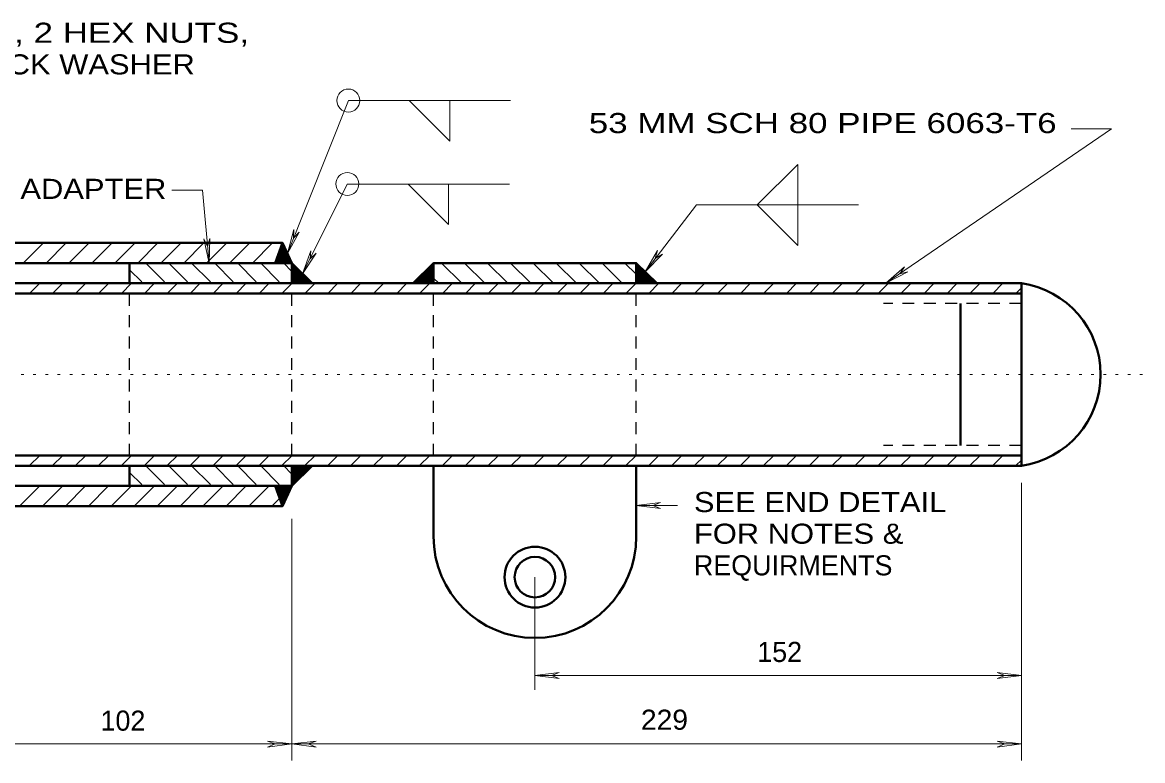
# Model space of a CAD drawing. Extents: x 312583 to 312854, y 144419 to 144597.
# Drawn here: x 312723.42 to 312765.79, y 144492.05 to 144519.98 of the extents above; entities that cross this region are included whole.
import ezdxf

# ---------------------------------------------------------------- set-up
doc = ezdxf.new("R2010")
doc.units = 0
doc.header["$LTSCALE"] = 0.3
doc.linetypes.add('DOTTED', pattern=[1.5, 0.3, -1.2])
doc.linetypes.add('SHORT_DASHED', pattern=[2.7, 1.5, -1.2])
doc.layers.add('1', color=7, linetype='Continuous', lineweight=13)

msp = doc.modelspace()

# ---------------------------------------------------------------- linework, layer by layer
at = {"layer": '1'}
for p, q in [((312735.7482, 144517.0229), (312733.4405, 144511.2346)), ((312741.8815, 144517.0229), (312735.7482, 144517.0229)), ((312756.0802, 144510.1076), (312764.6055, 144515.9572)), ((312763.0799, 144515.9572), (312764.6055, 144515.9572)), ((312735.7022, 144513.8642), (312734.0155, 144510.4679)), ((312741.8355, 144513.8642), (312735.7022, 144513.8642)), ((312748.9119, 144513.0746), (312746.9722, 144510.5446)), ((312755.0452, 144513.0746), (312748.9119, 144513.0746)), ((312733.4405, 144511.2346), (312733.6782, 144512.1392)), ((312733.4405, 144511.2346), (312733.8852, 144512.0472)), ((312733.6782, 144512.1392), (312733.6705, 144511.8172)), ((312733.8852, 144512.0472), (312733.6705, 144511.8172)), ((312723.4432, 144510.8742), (312724.2099, 144511.6409)), ((312724.3095, 144510.8742), (312725.0762, 144511.6409)), ((312725.1759, 144510.8742), (312725.9425, 144511.6409)), ((312726.0422, 144510.8742), (312726.8089, 144511.6409)), ((312726.9162, 144510.8742), (312727.6752, 144511.6409)), ((312727.7825, 144510.8742), (312728.5415, 144511.6409)), ((312728.6489, 144510.8742), (312729.4155, 144511.6409)), ((312729.5152, 144510.8742), (312730.2819, 144511.6409)), ((312730.2742, 144511.7866), (312730.4199, 144511.5029)), ((312730.4735, 144510.8742), (312730.2742, 144511.7866)), ((312730.3815, 144510.8742), (312731.1482, 144511.6409)), ((312730.5042, 144511.8019), (312730.4199, 144511.5029)), ((312730.4735, 144510.8742), (312730.5042, 144511.8019)), ((312731.2479, 144510.8742), (312732.0145, 144511.6409)), ((312732.1142, 144510.8742), (312732.8809, 144511.6409)), ((312732.9882, 144510.8742), (312733.3945, 144511.2882)), ((312734.0155, 144510.4679), (312734.3299, 144511.3419)), ((312734.0155, 144510.4679), (312734.5292, 144511.2422)), ((312734.3299, 144511.3419), (312734.2992, 144511.0352)), ((312734.5292, 144511.2422), (312734.2992, 144511.0352)), ((312746.9722, 144510.5446), (312747.4399, 144511.3496)), ((312746.9722, 144510.5446), (312747.6239, 144511.2116)), ((312747.4399, 144511.3496), (312747.3555, 144511.0506)), ((312747.6239, 144511.2116), (312747.3555, 144511.0506)), ((312728.7945, 144510.1689), (312728.0815, 144510.8742)), ((312729.6609, 144510.1689), (312728.9479, 144510.8742)), ((312730.5272, 144510.1689), (312729.8142, 144510.8742)), ((312731.3935, 144510.1689), (312730.6882, 144510.8742)), ((312732.2599, 144510.1689), (312731.5469, 144510.8819)), ((312733.1262, 144510.1689), (312732.4209, 144510.8819)), ((312733.6092, 144510.5522), (312733.2872, 144510.8819)), ((312740.0339, 144510.1076), (312739.2672, 144510.8742)), ((312740.9002, 144510.1076), (312740.1335, 144510.8742)), ((312741.7742, 144510.1076), (312741.0075, 144510.8742)), ((312742.6405, 144510.1076), (312741.8739, 144510.8742)), ((312743.5069, 144510.1076), (312742.7402, 144510.8742)), ((312744.3732, 144510.1076), (312743.6065, 144510.8742)), ((312745.2395, 144510.1076), (312744.4729, 144510.8742)), ((312746.1059, 144510.1076), (312745.3392, 144510.8742)), ((312746.6349, 144510.4526), (312746.2055, 144510.8742)), ((312756.0802, 144510.1076), (312756.7779, 144510.7286)), ((312756.7779, 144510.7286), (312756.6015, 144510.4679)), ((312727.9282, 144510.1689), (312727.4682, 144510.6212)), ((312739.1675, 144510.1076), (312738.9682, 144510.3069)), ((312756.0802, 144510.1076), (312756.9082, 144510.5369)), ((312756.9082, 144510.5369), (312756.6015, 144510.4679)), ((312723.6885, 144509.7242), (312724.0719, 144510.1076)), ((312724.5549, 144509.7242), (312724.9382, 144510.1076)), ((312725.4289, 144509.7242), (312725.8122, 144510.1076)), ((312726.2952, 144509.7242), (312726.6785, 144510.1076)), ((312727.1615, 144509.7242), (312727.5449, 144510.1076)), ((312728.0279, 144509.7242), (312728.4112, 144510.1076)), ((312728.8942, 144509.7242), (312729.2775, 144510.1076)), ((312729.7605, 144509.7242), (312730.1439, 144510.1076)), ((312730.6269, 144509.7242), (312731.0102, 144510.1076)), ((312731.5009, 144509.7242), (312731.8842, 144510.1076)), ((312732.3672, 144509.7242), (312732.7505, 144510.1076)), ((312733.2335, 144509.7242), (312733.6169, 144510.1076)), ((312734.0999, 144509.7242), (312734.4832, 144510.1076)), ((312734.9662, 144509.7242), (312735.3495, 144510.1076)), ((312735.8325, 144509.7242), (312736.2159, 144510.1076)), ((312736.6989, 144509.7242), (312737.0822, 144510.1076)), ((312737.5729, 144509.7242), (312737.9562, 144510.1076)), ((312738.4392, 144509.7242), (312738.8225, 144510.1076)), ((312739.3055, 144509.7242), (312739.6889, 144510.1076)), ((312740.1719, 144509.7242), (312740.5552, 144510.1076)), ((312741.0382, 144509.7242), (312741.4215, 144510.1076)), ((312741.9045, 144509.7242), (312742.2879, 144510.1076)), ((312742.7709, 144509.7242), (312743.1542, 144510.1076)), ((312743.6449, 144509.7242), (312744.0282, 144510.1076)), ((312744.5035, 144509.7242), (312744.8945, 144510.1076)), ((312745.3775, 144509.7242), (312745.7609, 144510.1076)), ((312746.2439, 144509.7242), (312746.6272, 144510.1076)), ((312747.1102, 144509.7242), (312747.4935, 144510.1076)), ((312747.9765, 144509.7242), (312748.3599, 144510.1076)), ((312748.8429, 144509.7242), (312749.2262, 144510.1076)), ((312749.7092, 144509.7242), (312750.0925, 144510.1076)), ((312750.5755, 144509.7242), (312750.9589, 144510.1076)), ((312751.4495, 144509.7242), (312751.8329, 144510.1076)), ((312752.3159, 144509.7242), (312752.6992, 144510.1076)), ((312753.1822, 144509.7242), (312753.5655, 144510.1076)), ((312754.0485, 144509.7242), (312754.4319, 144510.1076)), ((312754.9149, 144509.7242), (312755.2982, 144510.1076)), ((312755.7812, 144509.7242), (312756.1722, 144510.1076)), ((312756.6475, 144509.7242), (312757.0309, 144510.1076)), ((312757.5215, 144509.7242), (312757.9049, 144510.1076)), ((312758.3879, 144509.7242), (312758.7712, 144510.1076)), ((312759.2542, 144509.7242), (312759.6375, 144510.1076)), ((312760.1205, 144509.7242), (312760.5039, 144510.1076)), ((312760.9869, 144509.7242), (312761.2015, 144509.9389)), ((312723.6885, 144503.2152), (312724.0719, 144503.5986)), ((312724.5549, 144503.2152), (312724.9382, 144503.5986)), ((312725.4289, 144503.2152), (312725.8122, 144503.5986)), ((312726.2952, 144503.2152), (312726.6785, 144503.5986)), ((312727.1615, 144503.2152), (312727.5449, 144503.5986)), ((312728.0279, 144503.2152), (312728.4112, 144503.5986)), ((312728.8942, 144503.2152), (312729.2775, 144503.5986)), ((312729.7605, 144503.2152), (312730.1439, 144503.5986)), ((312730.6269, 144503.2152), (312731.0102, 144503.5986)), ((312731.5009, 144503.2152), (312731.8842, 144503.5986)), ((312732.3672, 144503.2152), (312732.7505, 144503.5986)), ((312733.2335, 144503.2152), (312733.6169, 144503.5986)), ((312734.0999, 144503.2152), (312734.4832, 144503.5986)), ((312734.9662, 144503.2152), (312735.3495, 144503.5986)), ((312735.8325, 144503.2152), (312736.2159, 144503.5986)), ((312736.6989, 144503.2152), (312737.0822, 144503.5986)), ((312737.5729, 144503.2152), (312737.9562, 144503.5986)), ((312738.4392, 144503.2152), (312738.8225, 144503.5986)), ((312739.3055, 144503.2152), (312739.6889, 144503.5986)), ((312740.1719, 144503.2152), (312740.5552, 144503.5986)), ((312741.0382, 144503.2152), (312741.4215, 144503.5986)), ((312741.9045, 144503.2152), (312742.2879, 144503.5986)), ((312742.7709, 144503.2152), (312743.1542, 144503.5986)), ((312743.6449, 144503.2152), (312744.0282, 144503.5986)), ((312744.5035, 144503.2152), (312744.8945, 144503.5986)), ((312745.3775, 144503.2152), (312745.7609, 144503.5986)), ((312746.2439, 144503.2152), (312746.6272, 144503.5986)), ((312747.1102, 144503.2152), (312747.4935, 144503.5986)), ((312747.9765, 144503.2152), (312748.3599, 144503.5986)), ((312748.8429, 144503.2152), (312749.2262, 144503.5909)), ((312749.7092, 144503.2152), (312750.0925, 144503.5909)), ((312750.5755, 144503.2152), (312750.9589, 144503.5986)), ((312751.4495, 144503.2152), (312751.8329, 144503.5986)), ((312752.3159, 144503.2152), (312752.6992, 144503.5986)), ((312753.1822, 144503.2152), (312753.5655, 144503.5986)), ((312754.0485, 144503.2152), (312754.4319, 144503.5986)), ((312754.9149, 144503.2152), (312755.2982, 144503.5986)), ((312755.7812, 144503.2152), (312756.1722, 144503.5986)), ((312756.6475, 144503.2152), (312757.0309, 144503.5986)), ((312757.5215, 144503.2152), (312757.9049, 144503.5986)), ((312758.3879, 144503.2152), (312758.7712, 144503.5986)), ((312759.2542, 144503.2152), (312759.6375, 144503.5986)), ((312760.1205, 144503.2152), (312760.5039, 144503.5986)), ((312728.7945, 144502.5022), (312728.0815, 144503.2076)), ((312729.6609, 144502.5022), (312728.9479, 144503.2076)), ((312730.5272, 144502.5022), (312729.8142, 144503.2076)), ((312731.3935, 144502.5022), (312730.6882, 144503.2076)), ((312732.2599, 144502.5022), (312731.5469, 144503.2152)), ((312733.1262, 144502.5022), (312732.4209, 144503.2152)), ((312733.6092, 144502.8856), (312733.2872, 144503.2152)), ((312760.9869, 144503.2152), (312761.2015, 144503.4222)), ((312727.9282, 144502.5022), (312727.4682, 144502.9546)), ((312723.3052, 144501.6742), (312724.0719, 144502.4409)), ((312724.1715, 144501.6742), (312724.9382, 144502.4409)), ((312725.0455, 144501.6742), (312725.8045, 144502.4409)), ((312725.9119, 144501.6742), (312726.6709, 144502.4409)), ((312726.7782, 144501.6742), (312727.5449, 144502.4409)), ((312727.6445, 144501.6742), (312728.4112, 144502.4409)), ((312728.5109, 144501.6742), (312729.2775, 144502.4409)), ((312729.3772, 144501.6742), (312730.1439, 144502.4409)), ((312730.2435, 144501.6742), (312731.0102, 144502.4409)), ((312731.1175, 144501.6742), (312731.8765, 144502.4409)), ((312731.9762, 144501.6742), (312732.7429, 144502.4409)), ((312732.8502, 144501.6742), (312733.6169, 144502.4409)), ((312761.2015, 144502.5559), (312761.2015, 144492.0526)), ((312746.6349, 144501.7049), (312747.5549, 144501.8199)), ((312747.5549, 144501.8199), (312747.2635, 144501.7049)), ((312748.1989, 144501.7049), (312746.6349, 144501.7049)), ((312746.6349, 144501.7049), (312747.5549, 144501.5899)), ((312747.5549, 144501.5899), (312747.2635, 144501.7049)), ((312733.6015, 144501.1989), (312733.6015, 144492.0526)), ((312742.8015, 144498.9909), (312742.8015, 144494.7282)), ((312742.8015, 144495.2726), (312743.7215, 144495.3876)), ((312742.8015, 144495.2726), (312761.2015, 144495.2726)), ((312742.8015, 144495.2726), (312743.7215, 144495.1576)), ((312743.7215, 144495.3876), (312743.4302, 144495.2726)), ((312743.7215, 144495.1576), (312743.4302, 144495.2726)), ((312760.2815, 144495.3876), (312760.5729, 144495.2726)), ((312761.2015, 144495.2726), (312760.2815, 144495.3876)), ((312760.2815, 144495.1576), (312760.5729, 144495.2726)), ((312761.2015, 144495.2726), (312760.2815, 144495.1576)), ((312732.6815, 144492.7886), (312732.9729, 144492.6812)), ((312733.6015, 144492.6812), (312732.6815, 144492.7886)), ((312732.6815, 144492.5662), (312732.9729, 144492.6812)), ((312733.6015, 144492.6812), (312732.6815, 144492.5662)), ((312733.6015, 144492.6812), (312734.5215, 144492.7886)), ((312733.6015, 144492.6812), (312734.5215, 144492.5662)), ((312734.5215, 144492.7886), (312734.2302, 144492.6812)), ((312734.5215, 144492.5662), (312734.2302, 144492.6812)), ((312760.2815, 144492.7886), (312760.5729, 144492.6812)), ((312761.2015, 144492.6812), (312760.2815, 144492.7886)), ((312760.2815, 144492.5662), (312760.5729, 144492.6812)), ((312761.2015, 144492.6812), (312760.2815, 144492.5662))]:
    msp.add_line(p, q, dxfattribs=at)
at = {"layer": '1', "lineweight": 40}
for p, q in [((312733.2565, 144511.6409), (312718.9199, 144511.6409)), ((312733.6015, 144510.8742), (312718.2069, 144510.8742)), ((312727.4682, 144510.1076), (312727.4682, 144510.8742)), ((312746.6349, 144510.8742), (312738.9682, 144510.8742)), ((312738.9682, 144510.1076), (312738.9682, 144510.8742)), ((312746.6349, 144510.1076), (312746.6349, 144510.8742)), ((312761.2015, 144510.1076), (312721.3349, 144510.1076)), ((312761.2015, 144503.2076), (312761.2015, 144510.1076)), ((312761.2015, 144509.7242), (312721.3349, 144509.7242)), ((312758.9015, 144503.9742), (312758.9015, 144509.3409)), ((312761.2015, 144503.5909), (312721.3349, 144503.5909)), ((312761.2015, 144503.2076), (312721.3349, 144503.2076)), ((312727.4682, 144502.4409), (312727.4682, 144503.2076)), ((312738.9682, 144500.5242), (312738.9682, 144503.2076)), ((312746.6349, 144500.5242), (312746.6349, 144503.2076)), ((312733.6015, 144502.4409), (312718.2069, 144502.4409))]:
    msp.add_line(p, q, dxfattribs=at)
at = {"layer": '1', "linetype": 'SHORT_DASHED', "lineweight": 25}
for p, q in [((312727.4682, 144503.5909), (312727.4682, 144509.7242)), ((312733.6015, 144503.5909), (312733.6015, 144509.7242)), ((312738.9682, 144503.5909), (312738.9682, 144509.7242)), ((312746.6349, 144503.5909), (312746.6349, 144509.7242)), ((312761.2015, 144509.3409), (312755.9805, 144509.3409)), ((312761.2015, 144503.9742), (312755.9805, 144503.9742))]:
    msp.add_line(p, q, dxfattribs=at)
at = {"layer": '1', "linetype": 'DOTTED'}
msp.add_line((312765.7862, 144506.6576), (312715.4622, 144506.6576), dxfattribs=at)
at = {"layer": '1'}
for points in [[(312738.0482, 144517.0229), (312739.5815, 144515.4896), (312739.5815, 144517.0229)], [(312751.2119, 144513.0746), (312752.7452, 144514.6079), (312752.7452, 144513.0746)], [(312738.0022, 144513.8642), (312739.5355, 144512.3309), (312739.5355, 144513.8642)], [(312730.4735, 144510.8742), (312730.2282, 144513.6342), (312729.0629, 144513.6342)], [(312751.2119, 144513.0746), (312752.7452, 144511.5412), (312752.7452, 144513.0746)], [(312721.3349, 144492.6812), (312733.6015, 144492.6812), (312761.2015, 144492.6812)]]:
    msp.add_lwpolyline(points, dxfattribs=at)
at = {"layer": '1', "lineweight": 40}
for points in [[(312733.6015, 144510.8742), (312733.2565, 144511.6332), (312732.9729, 144510.8742), (312733.6015, 144510.8742), (312733.2565, 144511.5412), (312733.0189, 144510.9049), (312733.5555, 144510.9049), (312733.2565, 144511.4569), (312733.0725, 144510.9356), (312733.5019, 144510.9432), (312733.2565, 144511.3726), (312733.1109, 144510.9739), (312733.4482, 144510.9739), (312733.2642, 144511.2959), (312733.1645, 144511.0046), (312733.3869, 144510.9969), (312733.2565, 144511.1962), (312733.2182, 144511.0582), (312733.3179, 144511.0352), (312733.2949, 144511.0736)], [(312733.6015, 144510.8742), (312734.3759, 144510.1152), (312733.6015, 144510.1152), (312733.6015, 144510.8742), (312734.2915, 144510.1536), (312733.6322, 144510.1459), (312733.6245, 144510.8052), (312734.2302, 144510.1842), (312733.6629, 144510.1842), (312733.6552, 144510.7132), (312734.1382, 144510.2149), (312733.6935, 144510.2149), (312733.6859, 144510.6366), (312734.0615, 144510.2456), (312733.7242, 144510.2532), (312733.7089, 144510.5676), (312733.9772, 144510.2839), (312733.7625, 144510.2839), (312733.7395, 144510.4986), (312733.9005, 144510.3222), (312733.7855, 144510.3222), (312733.7625, 144510.4219), (312733.8315, 144510.3452), (312733.8009, 144510.3529)], [(312738.9682, 144510.8742), (312738.1939, 144510.1152), (312738.9682, 144510.1152), (312738.9682, 144510.8742), (312738.2782, 144510.1536), (312738.9375, 144510.1459), (312738.9452, 144510.8052), (312738.3395, 144510.1842), (312738.9069, 144510.1842), (312738.9145, 144510.7132), (312738.4315, 144510.2149), (312738.8762, 144510.2149), (312738.8839, 144510.6366), (312738.5082, 144510.2456), (312738.8455, 144510.2532), (312738.8609, 144510.5676), (312738.5925, 144510.2839), (312738.8072, 144510.2839), (312738.8302, 144510.4986), (312738.6692, 144510.3222), (312738.7842, 144510.3222), (312738.8072, 144510.4219), (312738.7382, 144510.3452), (312738.7689, 144510.3529)], [(312746.6349, 144510.8742), (312747.4092, 144510.1152), (312746.6349, 144510.1152), (312746.6349, 144510.8742), (312747.3249, 144510.1536), (312746.6655, 144510.1459), (312746.6579, 144510.8052), (312747.2635, 144510.1842), (312746.6962, 144510.1842), (312746.6885, 144510.7132), (312747.1715, 144510.2149), (312746.7269, 144510.2149), (312746.7192, 144510.6366), (312747.0949, 144510.2456), (312746.7575, 144510.2532), (312746.7422, 144510.5676), (312747.0105, 144510.2839), (312746.7959, 144510.2839), (312746.7729, 144510.4986), (312746.9339, 144510.3222), (312746.8189, 144510.3222), (312746.7959, 144510.4219), (312746.8649, 144510.3452), (312746.8342, 144510.3529)], [(312733.6015, 144502.4409), (312734.3759, 144503.1999), (312733.6015, 144503.1999), (312733.6015, 144502.4409), (312734.2915, 144503.1692), (312733.6322, 144503.1692), (312733.6245, 144502.5176), (312734.2302, 144503.1386), (312733.6629, 144503.1309), (312733.6552, 144502.6096), (312734.1382, 144503.1002), (312733.6935, 144503.1079), (312733.6859, 144502.6786), (312734.0615, 144503.0696), (312733.7242, 144503.0696), (312733.7089, 144502.7552), (312733.9772, 144503.0389), (312733.7625, 144503.0312), (312733.7395, 144502.8166), (312733.9005, 144503.0006), (312733.7855, 144503.0006), (312733.7625, 144502.9009), (312733.8315, 144502.9699), (312733.8009, 144502.9699)], [(312733.2565, 144501.6742), (312717.8235, 144501.6742), (312718.2069, 144502.4409)], [(312733.6015, 144502.4409), (312733.2565, 144501.6819), (312732.9729, 144502.4409), (312733.6015, 144502.4409), (312733.2565, 144501.7739), (312733.0189, 144502.4102), (312733.5555, 144502.4179), (312733.2565, 144501.8659), (312733.0725, 144502.3796), (312733.5019, 144502.3796), (312733.2565, 144501.9426), (312733.1109, 144502.3489), (312733.4482, 144502.3489), (312733.2642, 144502.0192), (312733.1645, 144502.3106), (312733.3869, 144502.3259), (312733.2565, 144502.1189), (312733.2182, 144502.2569), (312733.3179, 144502.2799), (312733.2949, 144502.2492)]]:
    msp.add_lwpolyline(points, dxfattribs=at)
at = {"layer": '1'}
for centre in [(312735.7451, 144517.0214), (312735.7053, 144513.8658)]:
    msp.add_circle(centre, 0.4336, dxfattribs=at)
at = {"layer": '1', "lineweight": 40}
for radius in [1.15, 0.7667]:
    msp.add_circle((312742.8015, 144498.9924), radius, dxfattribs=at)
for centre, radius, start, end in [((312760.7139, 144506.6591), 3.4843, 278.04577, 81.95422), ((312742.8015, 144500.5258), 3.8333, 180, 0)]:
    msp.add_arc(centre, radius, start, end, dxfattribs=at)

# ---------------------------------------------------------------- texts
at = {"layer": '1'}
for s, width, p in [('THD LG. 2 X DIA. + 6 MM-0, 2 HEX NUTS,', 1.3, (312706.6229, 144519.2059)), ('2 FLAT WASHERS, & ONE LOCK WASHER', 1.15, (312706.6229, 144518.0089)), ('53 MM SCH 80 PIPE 6063-T6', 1.3, (312744.8378, 144515.7896)), ('CAST ALUM.  ADAPTER', 1.15, (312715.6766, 144513.2999)), ('SEE END DETAIL', 1.15, (312748.8141, 144501.453)), ('FOR NOTES &', 1.15, (312748.8141, 144500.256)), ('229', 1.05, (312746.8111, 144493.2199))]:
    msp.add_text(s, height=0.76, dxfattribs=dict(at, width=width)).set_placement(p)
for s, p in [('REQUIRMENTS', (312748.8141, 144499.059)), ('152', (312751.2106, 144495.7834)), ('102', (312726.3697, 144493.1843))]:
    msp.add_text(s, height=0.76, dxfattribs=at).set_placement(p)

doc.saveas('drawing.dxf')
